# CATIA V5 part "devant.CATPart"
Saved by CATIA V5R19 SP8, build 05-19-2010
Part number: Part1.1.2.3
Bounding box of the stored display mesh (mm): x 0 to 10, y -1110 to 150, z 0 to 580
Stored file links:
  G:\EU_thinkMotion\CFAO_2010\SIL_groupe2\SIL_groupe2\A reprendre\fnongaibaa\fnongaibaa\devant.CATPart
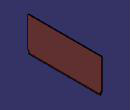
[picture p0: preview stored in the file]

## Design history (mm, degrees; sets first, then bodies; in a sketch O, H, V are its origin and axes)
Body1 (main body)
  Sketch1 on yz-plane, origin (0, 0, 0), H (0, 1, 0), V (0, 0, 1)
    line L1 (-1110, 580) -> (150, 580)
    line L2 (150, 580) -> (150, 0)
    line L3 (150, 0) -> (-1110, 0)
    line L4 (-1110, 0) -> (-1110, 580)
    length L3 = 1260
    length L2 = 580
    horizontal: L1 H, L3 H
    vertical: L2 V, L4 V
  Pad1: profile Sketch1, direction (1, 0, 0), length 10
  Sketch2 on face of Pad1 from Sketch1.L2, origin (4.6595, 150, 12.2344), H (1, 0, 0), V (0, 0, -1)
    point P1 (0.3405, -2.7656)
    reference projected line E1 (-4.6595, 12.2344) -> (5.3405, 12.2344) from edge [face of Pad1 from Sketch1.L2 | face of Pad1 from Sketch1.L3]
    axis line L1 (0.3405, 80.1829) -> (0.3405, -60.1738)
    reference projected line E2 (5.3405, 12.2344) -> (5.3405, -677.7656) from edge [face of Pad1 from Sketch1.L2 | end face of Pad1]
    reference projected line E3 (-4.6595, -677.7656) -> (-4.6595, 12.2344) from Sketch1.L4
    distance P1 E1 = 15
    symmetry: E2 E3 L1
    coincidence: P1 L1
  Hole1: placed by Sketch2, at (5, 150, 15) direction (0, -1, 0), diameter 5, through (limit type 3)
  Sketch3 on end face of Pad1, origin (10, 0, 0), H (0, 1, 0), V (0, 0, 1)
    line L1 (-1110, 55) -> (-1090, 55)
    line L2 (-1090, 55) -> (-1090, 0)
    line L3 (-1090, 0) -> (-1110, 0)
    line L4 (-1110, 0) -> (-1110, 55)
    point P3 (-1090, 0)
    reference projected line E1 (-1110, 690) -> (-1110, 0) from Sketch1.L4
    line L5 (130, 55) -> (150, 55)
    line L6 (150, 55) -> (150, 0)
    line L7 (150, 0) -> (130, 0)
    line L8 (130, 0) -> (130, 55)
    reference projected line E2 (150, 0) -> (150, 690) from Sketch1.L2
    reference projected line E3 (-910, 0) -> (150, 0) from Sketch1.L3
    length L1 = 20
    length L2 = 55
    length L5 = 20
    length L8 = 55
    horizontal: L1 H, L3 H, L5 H, L7 H
    vertical: L2 V, L4 V, L6 V, L8 V
    coincidence: P3 H, L4 E1, L6 E2, L7 E3
  Pocket1: profile Sketch3, direction (-1, 0, 0), through (limit type 3)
